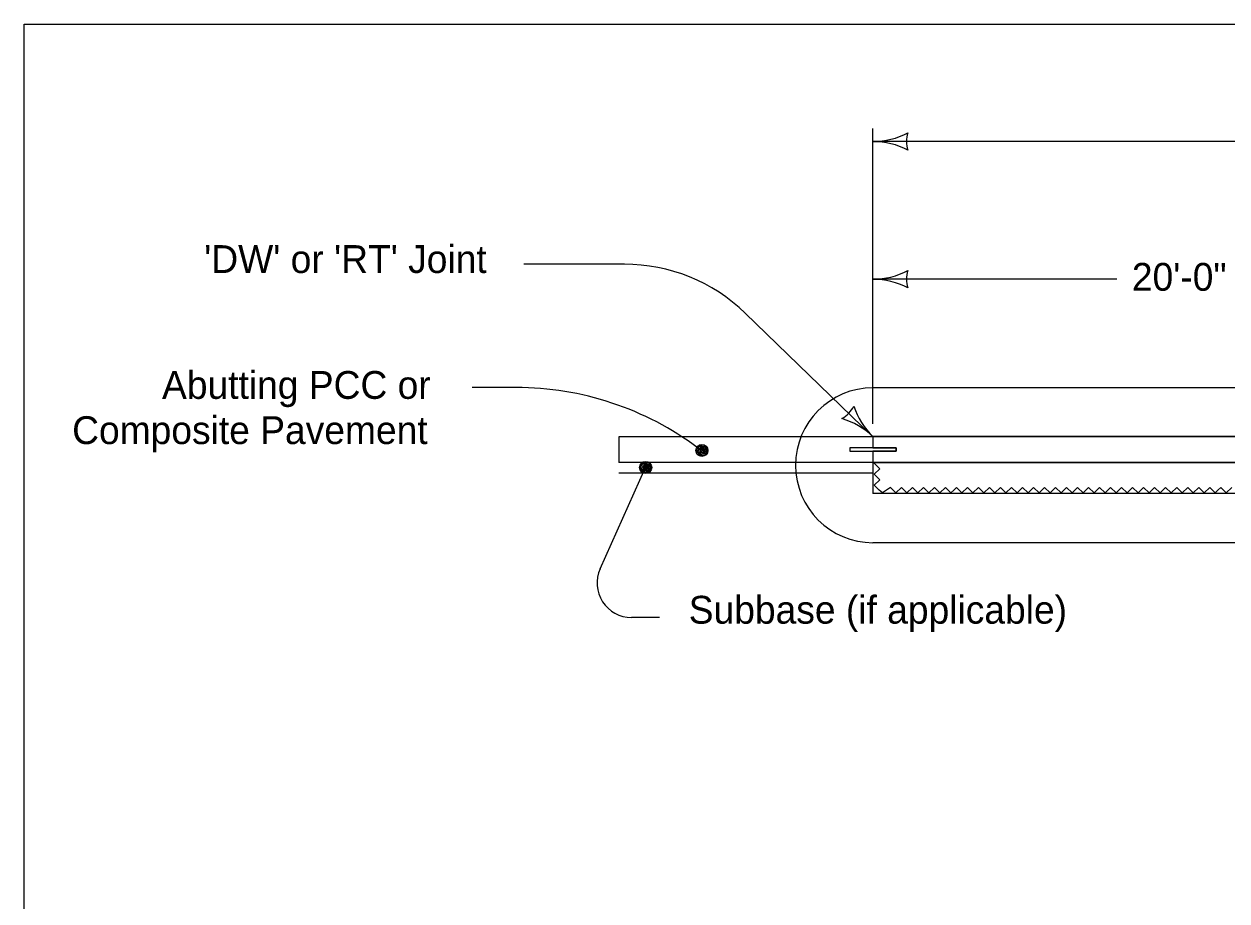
# Model space of a CAD drawing. Extents: x 5546 to 81668, y 3174 to 15999.
# Drawn here: x 13733 to 14425, y 9440 to 9944 of the extents above; entities that cross this region are included whole.
import ezdxf

# ---------------------------------------------------------------- set-up
doc = ezdxf.new("R2010")
doc.units = 0
for name, color, linetype in [('Level 61', 7, 'Continuous'), ('PS_BOLT', 7, 'Continuous'), ('PS_CONST', 7, 'Continuous'), ('PS_DAWA', 7, 'Continuous'), ('PS_DIM', 7, 'Continuous'), ('PS_SHAPE', 7, 'Continuous')]:
    doc.layers.add(name, color=color, linetype=linetype)

msp = doc.modelspace()

# ---------------------------------------------------------------- linework, layer by layer
at = {"layer": 'Level 61'}
msp.add_lwpolyline([(13732.52, 9944.02), (16867.53, 9944.02), (16867.53, 7924.02), (13732.52, 7924.02)], close=True, dxfattribs=at)
at = {"layer": 'PS_BOLT'}
for p, q in [((14577.37, 9706.74), (14220.97, 9706.74)), ((14220.97, 9706.74), (14220.97, 9700.25)), ((14120.33, 9700.18), (14121.33, 9699.44)), ((14220.97, 9700.25), (14234.34, 9700.24)), ((14234.34, 9698.39), (14220.97, 9698.39)), ((14220.97, 9698.39), (14220.97, 9691.89)), ((14234.34, 9700.24), (14234.34, 9698.39)), ((14220.97, 9691.89), (14577.37, 9691.89))]:
    msp.add_line(p, q, dxfattribs=at)
at = {"layer": 'PS_CONST'}
for p, q in [((14077.99, 9805.88), (14020.09, 9805.88)), ((14220.97, 9706.7), (14147.52, 9777.75)), ((14015.63, 9734.96), (13990.29, 9734.96)), ((14933.77, 9734.8), (14220.97, 9734.8)), ((14063.94, 9630.64), (14090.18, 9688.93)), ((14933.77, 9645.7), (14220.97, 9645.7)), ((14098.22, 9602.71), (14081.99, 9602.71))]:
    msp.add_line(p, q, dxfattribs=at)
for points in [[(14122.85, 9695.62), (14121.69, 9696.15), (14119.86, 9696.71), (14119.51, 9698.56), (14119.76, 9700.18), (14120.93, 9701.67), (14122.66, 9701.52), (14124.48, 9701.27), (14125.36, 9699.81), (14125.52, 9698.28), (14124.44, 9696.27), (14123.11, 9696.11), (14121.29, 9696.57), (14119.79, 9697.73), (14119.84, 9699.46), (14121, 9700.85), (14122.64, 9701.01), (14124.47, 9700.66), (14124.74, 9699.63), (14125.11, 9698.39), (14124.25, 9696.89), (14122.93, 9696.93), (14121.41, 9697.18), (14120.31, 9698.02), (14120.87, 9699.54), (14122.01, 9700.42), (14123.54, 9700.47), (14123.93, 9699.65), (14124.41, 9698.72), (14123.66, 9697.52), (14122.53, 9697.24), (14121.53, 9697.78), (14121.46, 9698.91), (14121.99, 9699.71), (14123.02, 9699.98), (14123.51, 9699.56), (14123.8, 9698.94), (14123.27, 9698.04), (14122.55, 9697.86), (14121.85, 9698.28), (14121.97, 9698.89), (14122.49, 9699.29), (14123.2, 9699.26), (14123.19, 9698.76), (14122.56, 9698.47)], [(14090.45, 9685.76), (14089.29, 9686.28), (14087.47, 9686.84), (14087.11, 9688.69), (14087.36, 9690.31), (14088.53, 9691.81), (14090.26, 9691.66), (14092.08, 9691.4), (14092.96, 9689.95), (14093.12, 9688.41), (14092.04, 9686.41), (14090.71, 9686.24), (14088.89, 9686.7), (14087.39, 9687.87), (14087.45, 9689.6), (14088.61, 9690.99), (14090.24, 9691.14), (14092.06, 9690.79), (14092.34, 9689.76), (14092.71, 9688.53), (14091.85, 9687.02), (14090.53, 9687.06), (14089.01, 9687.31), (14087.91, 9688.16), (14088.47, 9689.67), (14089.61, 9690.55), (14091.15, 9690.61), (14091.53, 9689.78), (14092.01, 9688.86), (14091.26, 9687.65), (14090.13, 9687.38), (14089.13, 9687.92), (14089.06, 9689.04), (14089.59, 9689.84), (14090.62, 9690.11), (14091.11, 9689.7), (14091.41, 9689.07), (14090.87, 9688.17), (14090.15, 9687.99), (14089.45, 9688.42), (14089.57, 9689.03), (14090.09, 9689.42), (14090.8, 9689.39), (14090.79, 9688.89), (14090.17, 9688.6)]]:
    msp.add_lwpolyline(points, dxfattribs=at)
for centre in [(14122.58, 9698.8), (14090.18, 9688.94)]:
    msp.add_circle(centre, 3.47, dxfattribs=at)
for centre, radius, start, end in [((14077.99, 9705.88), 100, 45.9504, 90), ((14015.63, 9559.96), 175, 53.25127, 90), ((14220.97, 9690.25), 44.55, 90, 270), ((14195.21, 9731.62), 16.51, 298.21686, 333.68356), ((14250.69, 9737.42), 42.75, 197.87772, 225.95021), ((14191.25, 9675.98), 42.75, 45.95021, 74.02269), ((14081.99, 9622.51), 19.8, 155.76197, 270)]:
    msp.add_arc(centre, radius, start, end, dxfattribs=at)
at = {"layer": 'PS_DAWA'}
for p, q in [((14220.97, 9714.12), (14220.97, 9883.89)), ((16092.07, 9876.46), (14220.97, 9876.46)), ((14361.3, 9797.26), (14220.97, 9797.26))]:
    msp.add_line(p, q, dxfattribs=at)
for centre, radius, start, end in [((14220.97, 9919.21), 42.75, 270, 298.07249), ((14256.81, 9876.46), 16.51, 162.26665, 197.73335), ((14220.97, 9833.71), 42.75, 61.92751, 90), ((14220.97, 9840.01), 42.75, 270, 298.07249), ((14220.97, 9840.01), 42.75, 270, 298.07249), ((14256.81, 9797.26), 16.51, 162.26665, 197.73335), ((14256.81, 9797.26), 16.51, 162.26665, 197.73335), ((14220.97, 9754.51), 42.75, 61.92751, 90), ((14220.97, 9754.51), 42.75, 61.92751, 90)]:
    msp.add_arc(centre, radius, start, end, dxfattribs=at)
at = {"layer": 'PS_DIM'}
for p, q in [((14220.97, 9706.7), (14074.79, 9706.7)), ((14074.79, 9706.7), (14074.79, 9691.85)), ((14220.97, 9706.7), (14220.97, 9700.2)), ((14930.39, 9706.7), (14220.97, 9706.7)), ((14234.34, 9700.2), (14207.61, 9700.2)), ((14207.61, 9700.2), (14207.61, 9698.34)), ((14207.61, 9698.34), (14234.34, 9698.34)), ((14220.97, 9698.34), (14220.97, 9691.85)), ((14234.34, 9698.34), (14234.34, 9700.2)), ((14220.97, 9691.85), (14074.79, 9691.85)), ((14220.97, 9691.85), (14220.97, 9674.03)), ((14931.39, 9691.85), (14220.97, 9691.85)), ((14074.79, 9685.91), (14220.97, 9685.91)), ((14926.35, 9674.03), (14220.97, 9674.03))]:
    msp.add_line(p, q, dxfattribs=at)
at = {"layer": 'PS_SHAPE'}
msp.add_line((14224.31, 9691.85), (14226.23, 9691.85), dxfattribs=at)
for points in [[(14224.61, 9675.84), (14221.7, 9678.75), (14224.87, 9681.91), (14221.7, 9685.08), (14224.87, 9688.25), (14221.71, 9691.42), (14222.14, 9691.85)], [(14267.42, 9675.96), (14265.84, 9674.37), (14262.67, 9677.55), (14259.5, 9674.38), (14256.33, 9677.55), (14253.17, 9674.38), (14250, 9677.55), (14246.83, 9674.38), (14243.66, 9677.55), (14240.49, 9674.39), (14237.33, 9677.55), (14234.16, 9674.39), (14230.99, 9677.55), (14226.44, 9674.39), (14224.61, 9675.84)], [(14343.45, 9675.93), (14341.87, 9674.35), (14338.7, 9677.52), (14335.53, 9674.35), (14332.37, 9677.52), (14329.2, 9674.35), (14326.03, 9677.52), (14322.86, 9674.35), (14319.69, 9677.52), (14316.53, 9674.36), (14313.36, 9677.53), (14310.19, 9674.36), (14307.02, 9677.53), (14303.85, 9674.36), (14300.69, 9677.53), (14297.52, 9674.37), (14294.35, 9677.53), (14291.18, 9674.37), (14288.01, 9677.53), (14284.85, 9674.37), (14281.68, 9677.54), (14278.51, 9674.37), (14275.34, 9677.54), (14272.17, 9674.37), (14269.01, 9677.54), (14267.42, 9675.96)], [(14419.49, 9675.9), (14417.9, 9674.32), (14414.73, 9677.49), (14411.57, 9674.32), (14408.4, 9677.49), (14405.23, 9674.32), (14402.06, 9677.49), (14398.89, 9674.33), (14395.73, 9677.49), (14392.56, 9674.33), (14389.39, 9677.5), (14386.22, 9674.33), (14383.05, 9677.5), (14379.89, 9674.33), (14376.72, 9677.5), (14373.55, 9674.34), (14370.38, 9677.51), (14367.21, 9674.34), (14364.05, 9677.51), (14360.88, 9674.34), (14357.71, 9677.51), (14354.54, 9674.35), (14351.37, 9677.51), (14348.21, 9674.35), (14345.04, 9677.51), (14343.45, 9675.93)], [(14427.41, 9677.49), (14424.24, 9674.32), (14421.07, 9677.49), (14419.49, 9675.9)]]:
    msp.add_lwpolyline(points, dxfattribs=at)

# ---------------------------------------------------------------- texts
at = {"layer": 'PS_CONST'}
for s, p in [("'DW' or 'RT' Joint", (13836.17, 9800.85)), ('Abutting PCC or', (13811.9, 9728.45)), ('Composite Pavement', (13760.19, 9702.45)), ('Subbase (if applicable)', (14114.98, 9599.15))]:
    msp.add_text(s, height=16, dxfattribs=at).set_placement(p)
at = {"layer": 'PS_DAWA'}
msp.add_text('20\'-0"', height=16, dxfattribs=at).set_placement((14369.95, 9790.63))

doc.saveas('drawing.dxf')
